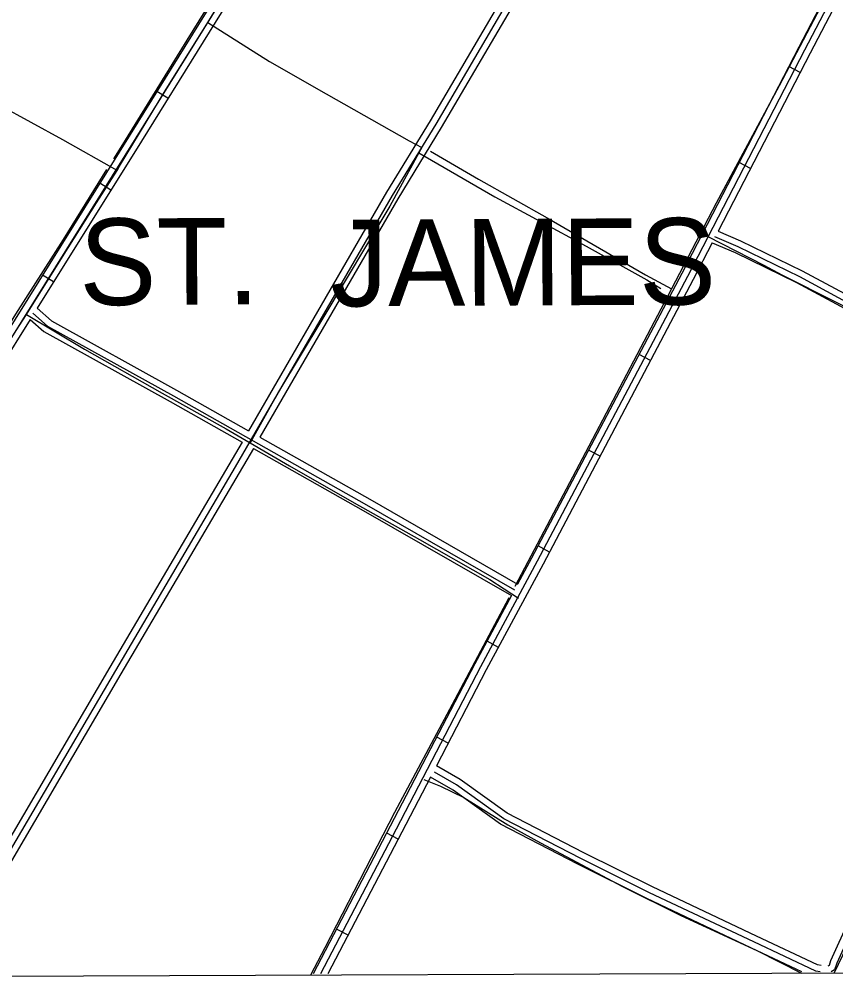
# Model space of a CAD drawing. Extents: x 3405885 to 3443815, y 558517 to 583997.
# Drawn here: x 3413116 to 3415002, y 563906 to 566129 of the extents above; entities that cross this region are included whole.
import ezdxf

# ---------------------------------------------------------------- set-up
doc = ezdxf.new("R2010")
doc.units = 0
for name, color, linetype in [('V-DTCH-CNTR', 7, 'Continuous'), ('V-GRID-FRAM', 7, 'Continuous'), ('V-ROAD-CNTR', 7, 'Continuous'), ('V-TOPO-GNAM-IDEN', 7, 'Continuous'), ('V-TOPO-SHOR', 7, 'Continuous')]:
    doc.layers.add(name, color=color, linetype=linetype)

msp = doc.modelspace()

# ---------------------------------------------------------------- linework, layer by layer
at = {"layer": 'V-DTCH-CNTR'}
for points in [[(3413108.5, 565410.3), (3413132.1, 565447), (3413215.7, 565580.3), (3413293.9, 565704.8), (3413341.5, 565780), (3413347.4, 565789.4), (3413455.1, 565967.9), (3413551.2, 566121.8), (3413559.6, 566135.3), (3413676.3, 566324.6), (3413761.2, 566461.8), (3413862.5, 566620.6), (3413943.1, 566746.9), (3414017.3, 566869), (3414018.5, 566871), (3414090.9, 566987.7), (3414194.6, 567150), (3414305, 567327.3)], [(3413341.5, 565780), (3413216.1, 565850.5), (3413069.4, 565930.5), (3412905.3, 566023.4), (3412719.2, 566127.8), (3412554.7, 566218.9)], [(3413551.2, 566121.8), (3413693.5, 566031.3), (3413824.7, 565956.9), (3414016.7, 565848.2), (3414045.8, 565833.2), (3414039, 565820.8), (3413971.7, 565697.3), (3413817, 565438.5), (3413714.6, 565268.2), (3413648.8, 565150.5)], [(3414039, 565820.8), (3414214.3, 565718.5), (3414425.7, 565604.9), (3414565.8, 565527.3), (3414598.3, 565506.9)], [(3414998.3, 563925.6), (3415119.6, 564176.6), (3415196.2, 564351.2), (3415372.2, 564728.7), (3415460.1, 564911.3), (3415536.2, 565064.1), (3415559.1, 565114), (3415504.7, 565167.2), (3415388.6, 565271.4), (3415354.3, 565297.2), (3415324.5, 565314.2), (3415234.8, 565360.2), (3415121.9, 565417.4), (3415003.9, 565474.6), (3414878.6, 565537.6), (3414836.4, 565560.4), (3414707.6, 565626.3)], [(3413132.3, 565447.4), (3413266.6, 565366.6), (3413446, 565265.3), (3413593.5, 565182.8), (3413648.8, 565150.5), (3413739.7, 565097.6), (3413889.8, 565012.3), (3414040.3, 564927.5), (3414202.8, 564834.8), (3414269.5, 564792.1)], [(3414050.6, 564373.1), (3414088.8, 564357.2), (3414143, 564331.7), (3414244.8, 564267.9), (3414319.7, 564226.3), (3414509.8, 564125.6), (3414644.6, 564058.9), (3414819.6, 563977.8), (3414923.4, 563925.3)]]:
    msp.add_lwpolyline(points, dxfattribs=at)
at = {"layer": 'V-GRID-FRAM'}
msp.add_lwpolyline([(3409954, 582088.9), (3441575.2, 582215.4), (3441655.9, 564032.2), (3410018.8, 563905.7), (3409954, 582088.9)], dxfattribs=at)
at = {"layer": 'V-ROAD-CNTR'}
for p, q in [((3414920.3, 566006.1), (3414893.7, 566019.9)), ((3413459.3, 565946.5), (3413433.9, 565962.4)), ((3414805.5, 565784.1), (3414778.8, 565797.8)), ((3413327.2, 565734.3), (3413301.7, 565750.2)), ((3414690.7, 565562), (3414664, 565575.8)), ((3413194.7, 565522.2), (3413169.3, 565538.1)), ((3414574.2, 565340.6), (3414547.7, 565354.6)), ((3414457.5, 565119.5), (3414431, 565133.5)), ((3414340.8, 564898.4), (3414314.3, 564912.4)), ((3414222.8, 564677.9), (3414196.4, 564692.1)), ((3414106.7, 564456.7), (3414080.1, 564470.6)), ((3413991.2, 564235), (3413964.6, 564248.9)), ((3413875.4, 564013.5), (3413848.8, 564027.4))]:
    msp.add_line(p, q, dxfattribs=at)
for points in [[(3416007.2, 570009.8), (3415967.4, 569979.6), (3415922.1, 569925.5), (3415803.1, 569736.3), (3415517.1, 569281.3), (3415248.2, 568844.8), (3414919.3, 568320.9), (3414602, 567811.3), (3414146.5, 567083.1), (3413812.9, 566544.5), (3413385.1, 565855.3), (3412987.3, 565218.5), (3412530.1, 564486.2), (3412173.6, 563917.5)], [(3416332.7, 569692.6), (3416288.6, 569645.2), (3416123.1, 569370.4), (3415869.9, 568936.4), (3415516.6, 568329.5), (3415264.4, 567902.5), (3414893.4, 567271.6), (3414699.3, 566943.5), (3414487.8, 566575.6), (3414385.7, 566411.5), (3414078, 565887), (3413977.1, 565722.2), (3413614.4, 565095.1), (3413337.8, 564624.9), (3413054.9, 564142.4), (3412922.6, 563920.5)], [(3416679.9, 569370.3), (3416645.1, 569338.3), (3416611, 569290.2), (3416557.8, 569182.4), (3416257.5, 568600.9), (3415941.7, 568000.8), (3415701.9, 567542.9), (3415367, 566904.6), (3415175.6, 566528.1), (3414930, 566057.5), (3414659.7, 565534.7), (3414312.6, 564877.1), (3414181.6, 564632.9), (3413986.2, 564257.8), (3413811.7, 563924.1)], [(3415779.8, 567653.6), (3415947.5, 567565.5), (3416277.7, 567377), (3416503.8, 567239.2), (3416549.6, 567203.3), (3416538.7, 567159.5), (3416392.9, 566873), (3416158.2, 566377.3), (3415972.7, 565990.5), (3415759.9, 565554.1), (3415520.2, 565047.4), (3415251, 564490.5), (3415004.4, 563948.6), (3414999, 563932.9), (3414991.3, 563928.8)], [(3414001.4, 566877.3), (3413800.1, 566552.4), (3413372.3, 565863.2), (3412974.6, 565226.4), (3412591.9, 564613.5)], [(3414022.4, 566854.3), (3413825.6, 566536.6), (3413397.8, 565847.4), (3413156.8, 565461.5)], [(3415251.9, 566645.1), (3415188.9, 566521.3), (3414943.3, 566050.6), (3414730.8, 565639.6)], [(3414448.5, 566540.8), (3414372.8, 566419.2), (3414065.1, 565894.7), (3413964.2, 565729.9), (3413645.3, 565178.5)], [(3414474.8, 566526.4), (3414398.5, 566403.7), (3414090.8, 565879.3), (3413990, 565714.6), (3413671.4, 565163.8)], [(3415001.8, 566227.6), (3414916.7, 566064.4), (3414646.4, 565541.7), (3414299.4, 564884.1), (3414267.1, 564824)], [(3414721.7, 565627.2), (3414775.7, 565603.8), (3414918.1, 565534.7), (3415070.2, 565452.7), (3415192.8, 565391), (3415292.6, 565343.2), (3415351.4, 565317.4), (3415403, 565283.3), (3415440.7, 565253.7), (3415501.4, 565191.3), (3415543.5, 565148.6), (3415556.9, 565126.5), (3415626, 565082.7), (3415725.7, 565034.5), (3415912.4, 564952.1), (3415984.4, 564921.5), (3416007.8, 564910.9)], [(3414730.8, 565639.6), (3414781.9, 565617.4), (3414924.9, 565548), (3415077.1, 565466), (3415199.4, 565404.5), (3415298.9, 565356.8), (3415358.6, 565330.6), (3415411.8, 565295.5), (3415450.8, 565264.8), (3415512.1, 565201.8), (3415555.7, 565157.6)], [(3414717, 565612.9), (3414673, 565527.8), (3414325.8, 564870), (3414194.8, 564625.9), (3414079.7, 564404.8)], [(3414717, 565612.9), (3414769.4, 565590.2), (3414911.2, 565521.3), (3415063.2, 565439.4), (3415186.2, 565377.6), (3415286.4, 565329.6), (3415344.2, 565304.2), (3415394.3, 565271.1), (3415430.7, 565242.5), (3415490.7, 565180.8), (3415531.6, 565139.3), (3415540.3, 565125)], [(3413147.1, 565450.1), (3413181.3, 565420.2), (3413471.7, 565259.2), (3413918, 565007.4), (3414260.2, 564810.7)], [(3413156.8, 565461.5), (3413189.9, 565432.5), (3413479, 565272.3), (3413645.3, 565178.5)], [(3413140.7, 565435.7), (3413000.1, 565210.5), (3412542.8, 564478.2), (3412192, 563918.5)], [(3413140.7, 565435.7), (3413172.6, 565407.8), (3413464.4, 565246.1), (3413630.6, 565152.3)], [(3413671.4, 565163.8), (3413925.5, 565020.5), (3414267.1, 564824)], [(3413630.6, 565152.3), (3413324.8, 564632.5), (3413042, 564150), (3412905.1, 563920.4)], [(3413656.8, 565137.6), (3413350.7, 564617.3), (3413067.8, 564134.7), (3412940.1, 563920.6)], [(3413656.8, 565137.6), (3413910.6, 564994.4), (3414252.9, 564797.6)], [(3415540.3, 565125), (3415506.6, 565053.9), (3415237.4, 564496.9), (3414990.4, 563954.2), (3414986.7, 563943.3), (3414984.2, 563942)], [(3414252.9, 564797.6), (3414168.3, 564639.9), (3413972.9, 564264.8), (3413794.7, 563924)], [(3414968.3, 563943.5), (3414960.1, 563944.6), (3414819, 564011.3), (3414578.4, 564124.9), (3414419.8, 564203.7), (3414243.1, 564295.2), (3414134.2, 564373.1), (3414079.7, 564404.8)], [(3414966.4, 563928.7), (3414955.8, 563930.1), (3414812.6, 563997.8), (3414571.9, 564111.4), (3414413, 564190.4), (3414235.3, 564282.4), (3414126, 564360.5), (3414075.3, 564390)], [(3414065.8, 564378.2), (3413999.5, 564250.9), (3413828.7, 563924.1)], [(3414924, 563928.5), (3414806.2, 563984.2), (3414565.3, 564097.9), (3414406.2, 564177), (3414227.4, 564269.5), (3414117.9, 564347.9), (3414065.8, 564378.2)]]:
    msp.add_lwpolyline(points, dxfattribs=at)
at = {"layer": 'V-TOPO-SHOR'}
for points in [[(3413999.1, 566864.2), (3413983.6, 566845.1), (3413965.8, 566819.2), (3413902.9, 566717.6), (3413774.4, 566510.7), (3413604, 566243.9), (3413502.7, 566080.6), (3413360.6, 565850), (3413333.1, 565806.5)], [(3414998.9, 566217.7), (3414871.2, 565975.6), (3414725.8, 565704.4), (3414622.8, 565506), (3414614.5, 565490), (3414423.7, 565128.4), (3414260.6, 564819)], [(3414065.5, 565824.1), (3414177, 565759.5), (3414335.7, 565670.5), (3414562.8, 565539), (3414622.8, 565506)], [(3413317.2, 565781.7), (3413217, 565620.2), (3413107.2, 565448.1), (3412991.5, 565261.8), (3412846.7, 565023.9), (3412679.8, 564755.6), (3412586.2, 564607.9)], [(3414246.6, 564792.5), (3414116.1, 564546.2), (3413982.9, 564296.5), (3413821.7, 563984), (3413788.5, 563920.8)]]:
    msp.add_lwpolyline(points, dxfattribs=at)

# ---------------------------------------------------------------- texts
at = {"layer": 'V-TOPO-GNAM-IDEN'}
for s, rotation, p in [('ST.', 0.248, (3413254.6, 565468.6)), ('JAMES', 0.2993, (3413834.4, 565465.6))]:
    msp.add_text(s, height=200, rotation=rotation, dxfattribs=at).set_placement(p)

doc.saveas('drawing.dxf')
